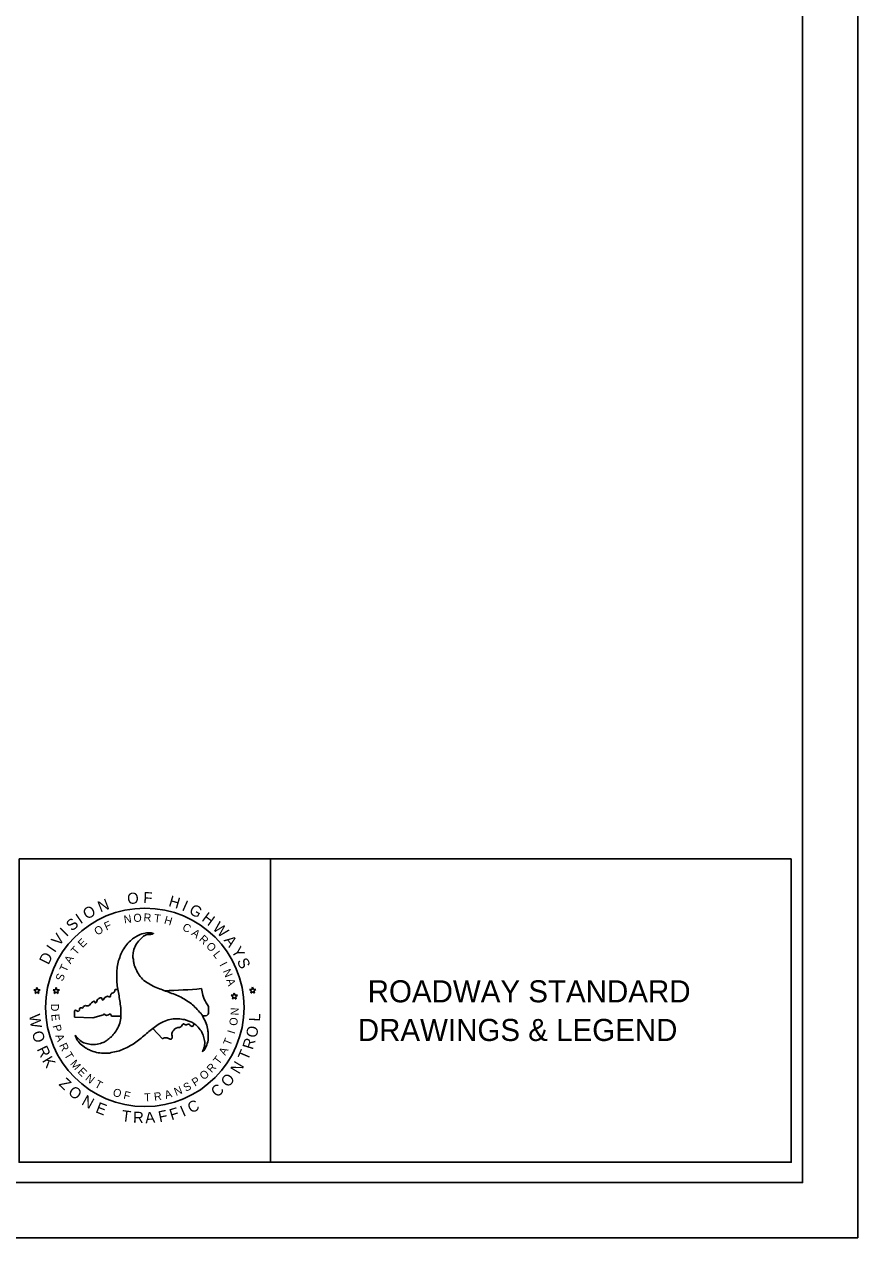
# Model space of a CAD drawing. Extents: x -0.1 to 33.8, y -19.9 to 2.3.
# Drawn here: x 26.19 to 33.78, y -19.85 to -8.8 of the extents above; entities that cross this region are included whole.
import ezdxf

# ---------------------------------------------------------------- set-up
doc = ezdxf.new("R2010")
doc.units = 0
for name, color, linetype in [('DEV DOT SWIRL SEAL CELL', 7, 'Continuous'), ('GSBWFILL', 7, 'Continuous'), ('GSOUTLINE', 7, 'Continuous'), ('Text', 7, 'Continuous')]:
    doc.layers.add(name, color=color, linetype=linetype)

msp = doc.modelspace()

# ---------------------------------------------------------------- linework, layer by layer
at = {"layer": 'DEV DOT SWIRL SEAL CELL'}
for p, q in [((26.301, -17.575), (26.295, -17.595)), ((26.309, -17.595), (26.301, -17.575)), ((26.476, -17.575), (26.469, -17.595)), ((26.483, -17.595), (26.476, -17.575)), ((28.266, -17.572), (28.259, -17.592)), ((28.273, -17.592), (28.266, -17.572)), ((26.273, -17.595), (26.291, -17.608)), ((26.295, -17.595), (26.273, -17.595)), ((26.291, -17.608), (26.284, -17.629)), ((26.284, -17.629), (26.301, -17.616)), ((26.301, -17.616), (26.319, -17.629)), ((26.301, -17.616), (26.319, -17.629)), ((26.33, -17.595), (26.309, -17.595)), ((26.313, -17.608), (26.33, -17.595)), ((26.313, -17.608), (26.33, -17.595)), ((26.319, -17.629), (26.313, -17.608)), ((26.319, -17.629), (26.313, -17.608)), ((26.469, -17.595), (26.448, -17.595)), ((26.448, -17.595), (26.465, -17.608)), ((26.465, -17.608), (26.459, -17.629)), ((26.459, -17.629), (26.476, -17.616)), ((26.476, -17.616), (26.494, -17.629)), ((26.505, -17.595), (26.483, -17.595)), ((26.487, -17.608), (26.505, -17.595)), ((26.494, -17.629), (26.487, -17.608)), ((28.093, -17.645), (28.071, -17.645)), ((28.071, -17.645), (28.089, -17.658)), ((28.089, -17.658), (28.082, -17.679)), ((28.082, -17.679), (28.099, -17.666)), ((28.099, -17.625), (28.093, -17.645)), ((28.107, -17.645), (28.099, -17.625)), ((28.099, -17.666), (28.117, -17.679)), ((28.128, -17.645), (28.107, -17.645)), ((28.111, -17.658), (28.128, -17.645)), ((28.117, -17.679), (28.111, -17.658)), ((28.259, -17.592), (28.237, -17.592)), ((28.237, -17.592), (28.255, -17.605)), ((28.255, -17.605), (28.249, -17.626)), ((28.249, -17.626), (28.266, -17.613)), ((28.266, -17.613), (28.283, -17.626)), ((28.295, -17.592), (28.273, -17.592)), ((28.277, -17.605), (28.295, -17.592)), ((28.283, -17.626), (28.277, -17.605)), ((26.642, -17.845), (26.643, -17.792)), ((26.81, -17.851), (26.642, -17.845)), ((26.907, -17.823), (26.81, -17.851)), ((26.981, -17.834), (27.066, -17.835)), ((27.358, -17.947), (27.445, -18.041))]:
    msp.add_line(p, q, dxfattribs=at)
for start, end in [(265.6785, 265.9762), (271.2035, 275.3236)]:
    msp.add_arc((27.366, -12.917), 4.687, start, end, dxfattribs=at)
for points in [[(26.65, -18.008), (26.685, -18.049), (26.729, -18.077), (26.779, -18.09), (26.835, -18.093), (26.893, -18.079), (26.931, -18.06), (26.948, -18.047), (26.976, -18.025), (26.996, -18.003), (27.029, -17.956), (27.055, -17.9), (27.066, -17.836), (27.066, -17.83), (27.066, -17.77), (27.058, -17.709), (27.049, -17.65), (27.038, -17.589), (27.029, -17.529), (27.028, -17.47), (27.031, -17.402), (27.041, -17.344), (27.06, -17.285), (27.07, -17.257), (27.084, -17.234), (27.119, -17.181), (27.165, -17.138), (27.195, -17.115), (27.224, -17.1), (27.229, -17.097), (27.286, -17.079), (27.342, -17.077), (27.361, -17.082)], [(27.363, -17.08), (27.361, -17.082), (27.309, -17.091), (27.262, -17.116), (27.226, -17.152), (27.195, -17.199), (27.178, -17.257), (27.175, -17.299), (27.179, -17.32), (27.184, -17.355), (27.192, -17.383), (27.217, -17.436), (27.252, -17.486), (27.303, -17.528), (27.308, -17.531), (27.359, -17.561), (27.417, -17.585), (27.472, -17.606), (27.53, -17.627), (27.587, -17.65), (27.639, -17.678), (27.696, -17.715), (27.74, -17.752), (27.782, -17.798), (27.802, -17.821), (27.814, -17.845), (27.843, -17.901), (27.857, -17.963), (27.862, -18.001), (27.861, -18.033), (27.861, -18.038), (27.848, -18.097), (27.821, -18.147), (27.808, -18.16)], [(26.643, -17.792), (26.642, -17.787), (26.651, -17.781), (26.676, -17.791), (26.688, -17.78), (26.688, -17.77), (26.698, -17.759), (26.715, -17.762), (26.73, -17.743), (26.744, -17.739), (26.774, -17.739), (26.81, -17.703), (26.825, -17.701), (26.829, -17.711), (26.838, -17.712), (26.854, -17.683), (26.858, -17.679), (26.885, -17.667), (26.893, -17.673), (26.895, -17.686), (26.899, -17.688), (26.908, -17.682), (26.92, -17.666), (26.943, -17.654), (26.969, -17.658), (26.974, -17.636), (27.004, -17.616), (27.011, -17.603), (27.012, -17.591)], [(27.807, -17.83), (27.856, -17.824), (27.864, -17.784), (27.864, -17.751), (27.844, -17.713), (27.813, -17.643), (27.801, -17.584)], [(27.808, -18.16), (27.826, -18.111), (27.828, -18.058), (27.814, -18.008), (27.789, -17.958), (27.748, -17.915), (27.713, -17.891), (27.693, -17.884), (27.66, -17.87), (27.631, -17.864), (27.574, -17.859), (27.512, -17.864), (27.451, -17.887), (27.446, -17.889), (27.394, -17.92), (27.345, -17.957), (27.298, -17.994), (27.251, -18.034), (27.203, -18.073), (27.153, -18.103), (27.092, -18.134), (27.038, -18.154), (26.977, -18.167), (26.947, -18.173), (26.921, -18.172), (26.858, -18.168), (26.797, -18.15), (26.762, -18.135), (26.735, -18.118), (26.73, -18.115), (26.685, -18.075), (26.656, -18.027), (26.65, -18.008)], [(26.981, -17.834), (26.974, -17.821), (26.961, -17.817), (26.942, -17.827), (26.928, -17.826), (26.913, -17.815), (26.907, -17.823)], [(27.445, -18.041), (27.479, -18.031), (27.507, -18.042), (27.521, -18.044), (27.532, -18.035), (27.529, -17.993), (27.538, -17.973), (27.584, -17.939), (27.613, -17.933), (27.634, -17.906), (27.642, -17.907), (27.655, -17.914), (27.684, -17.909), (27.708, -17.927), (27.721, -17.926), (27.732, -17.905)]]:
    msp.add_spline(points, degree=3, dxfattribs=at)
at = {"layer": 'GSBWFILL'}
msp.add_line((33.779, -19.853), (33.779, -19.853), dxfattribs=at)
for points in [[(33.276, 1.754), (3.126, 1.754), (3.126, -19.351), (33.276, -19.351)], [(26.138, -16.402), (28.429, -16.402), (28.429, -19.166), (26.138, -19.166)], [(33.173, -16.402), (28.429, -16.402), (28.429, -19.166), (33.173, -19.166)]]:
    msp.add_lwpolyline(points, close=True, dxfattribs=at)
at = {"layer": 'GSOUTLINE'}
msp.add_lwpolyline([(-0.15, 2.257), (33.779, 2.257), (33.779, -19.853), (-0.15, -19.853)], close=True, dxfattribs=at)
at = {"layer": 'Text'}
msp.add_circle((27.284, -17.755), 0.904, dxfattribs=at)

# ---------------------------------------------------------------- texts
at = {"layer": 'DEV DOT SWIRL SEAL CELL'}
for s, height, rotation, p in [('N', 0.101, 21.5861, (26.879, -16.891)), ('O', 0.101, 5.7649, (27.128, -16.816)), ('F', 0.101, 357.2575, (27.268, -16.804)), ('H', 0.101, 343.454, (27.494, -16.83)), ('I', 0.101, 335.804, (27.614, -16.868)), ('I', 0.101, 34.3808, (26.698, -16.999)), ('O', 0.101, 30.0935, (26.756, -16.958)), ('N', 0.0729, 9.0227, (27.098, -16.992)), ('O', 0.0729, 3.9446, (27.182, -16.978)), ('R', 0.0729, 358.8665, (27.272, -16.972)), ('G', 0.101, 331.5167, (27.679, -16.896)), ('H', 0.101, 323.4632, (27.795, -16.961)), ('S', 0.101, 40.5848, (26.62, -17.066)), ('O', 0.0729, 29.335, (26.848, -17.102)), ('F', 0.0729, 24.2569, (26.933, -17.055)), ('H', 0.0729, 343.6322, (27.454, -16.99)), ('C', 0.0729, 333.4761, (27.619, -17.048)), ('W', 0.101, 315.8133, (27.895, -17.038)), ('V', 0.101, 51.5806, (26.502, -17.203)), ('I', 0.101, 44.8722, (26.571, -17.117)), ('E', 0.0729, 44.5692, (26.716, -17.216)), ('A', 0.0729, 323.3199, (27.702, -17.091)), ('R', 0.0729, 318.2418, (27.772, -17.142)), ('A', 0.101, 306.7762, (27.999, -17.144)), ('I', 0.101, 55.8679, (26.463, -17.262)), ('T', 0.0729, 49.6473, (26.658, -17.283)), ('O', 0.0729, 313.1637, (27.837, -17.201)), ('L', 0.0729, 308.0856, (27.901, -17.275)), ('Y', 0.101, 299.7484, (28.068, -17.238)), ('D', 0.101, 63.459, (26.406, -17.373)), ('A', 0.0729, 59.8035, (26.607, -17.363)), ('I', 0.0729, 297.9295, (27.962, -17.365)), ('S', 0.101, 293.2249, (28.121, -17.331)), ('S', 0.0729, 69.9597, (26.536, -17.523)), ('T', 0.0729, 64.8816, (26.568, -17.439)), ('N', 0.0729, 292.8514, (27.993, -17.424)), ('A', 0.0729, 287.7733, (28.025, -17.505)), ('D', 0.0729, 270.272, (26.428, -17.721)), ('N', 0.0729, 87.733, (28.137, -17.829)), ('E', 0.0729, 275.3501, (26.431, -17.818)), ('O', 0.0729, 82.9269, (28.124, -17.926)), ('P', 0.0729, 285.5063, (26.443, -17.923)), ('A', 0.0729, 290.5843, (26.467, -18.013)), ('I', 0.0729, 72.7707, (28.102, -18.002)), ('R', 0.0729, 295.6624, (26.501, -18.1)), ('T', 0.0729, 67.6926, (28.062, -18.11)), ('T', 0.0729, 300.7405, (26.546, -18.188)), ('M', 0.0729, 310.8967, (26.599, -18.271)), ('T', 0.0729, 52.4584, (27.958, -18.281)), ('A', 0.0729, 62.6145, (28.017, -18.198)), ('E', 0.0729, 315.9748, (26.666, -18.347)), ('O', 0.0729, 42.3022, (27.822, -18.421)), ('R', 0.0729, 47.3803, (27.893, -18.356)), ('N', 0.0729, 321.0529, (26.735, -18.411)), ('T', 0.0729, 331.209, (26.82, -18.476)), ('S', 0.0729, 27.068, (27.657, -18.525)), ('P', 0.0729, 32.146, (27.74, -18.478)), ('O', 0.0729, 341.3652, (26.985, -18.557)), ('F', 0.0729, 346.4433, (27.084, -18.586)), ('T', 0.0729, 1.6775, (27.28, -18.611)), ('R', 0.0729, 6.7556, (27.371, -18.606)), ('A', 0.0729, 16.9118, (27.476, -18.59)), ('N', 0.0729, 21.9899, (27.568, -18.562))]:
    msp.add_text(s, height=height, rotation=rotation, dxfattribs=at).set_placement(p)
at = {"layer": 'GSBWFILL'}
for s, p in [('ROADWAY STANDARD ', (29.314, -17.709)), ('DRAWINGS & LEGEND', (29.224, -18.061))]:
    msp.add_text(s, height=0.201, dxfattribs=at).set_placement(p)
at = {"layer": 'Text'}
for s, height, rotation, p in [('T', 0.0729, 353.7884, (27.365, -16.977)), ('W', 0.101, 278.15, (26.229, -17.823)), ('L', 0.101, 87.429, (28.333, -17.885)), ('O', 0.101, 287.1147, (26.252, -17.986)), ('O', 0.101, 78.9896, (28.302, -18.037)), ('R', 0.101, 295.5541, (26.297, -18.135)), ('R', 0.101, 72.7519, (28.266, -18.146)), ('K', 0.101, 301.7918, (26.344, -18.24)), ('T', 0.101, 66.881, (28.221, -18.245)), ('N', 0.101, 58.892, (28.143, -18.37)), ('Z', 0.101, 316.1688, (26.494, -18.458)), ('C', 0.101, 43.0807, (27.943, -18.581)), ('O', 0.101, 50.4526, (28.044, -18.49)), ('O', 0.101, 322.5233, (26.577, -18.541)), ('N', 0.101, 330.9626, (26.7, -18.636)), ('E', 0.101, 338.9517, (26.828, -18.709)), ('F', 0.101, 17.7627, (27.527, -18.784)), ('I', 0.101, 23.7503, (27.633, -18.753)), ('C', 0.101, 28.0033, (27.706, -18.724)), ('T', 0.101, 352.6948, (27.068, -18.79)), ('R', 0.101, 358.5656, (27.175, -18.806)), ('A', 0.101, 4.8034, (27.29, -18.812)), ('F', 0.101, 11.7751, (27.418, -18.803))]:
    msp.add_text(s, height=height, rotation=rotation, dxfattribs=at).set_placement(p)

doc.saveas('drawing.dxf')
